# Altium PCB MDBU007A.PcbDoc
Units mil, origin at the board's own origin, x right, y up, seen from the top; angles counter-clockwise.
Board outline 3500 x 3000 mil, 2 copper layers (Top Layer, Bottom Layer), stack 63.4 mil thick; 53 components, 17 nets, 100 pads, 108 vias.
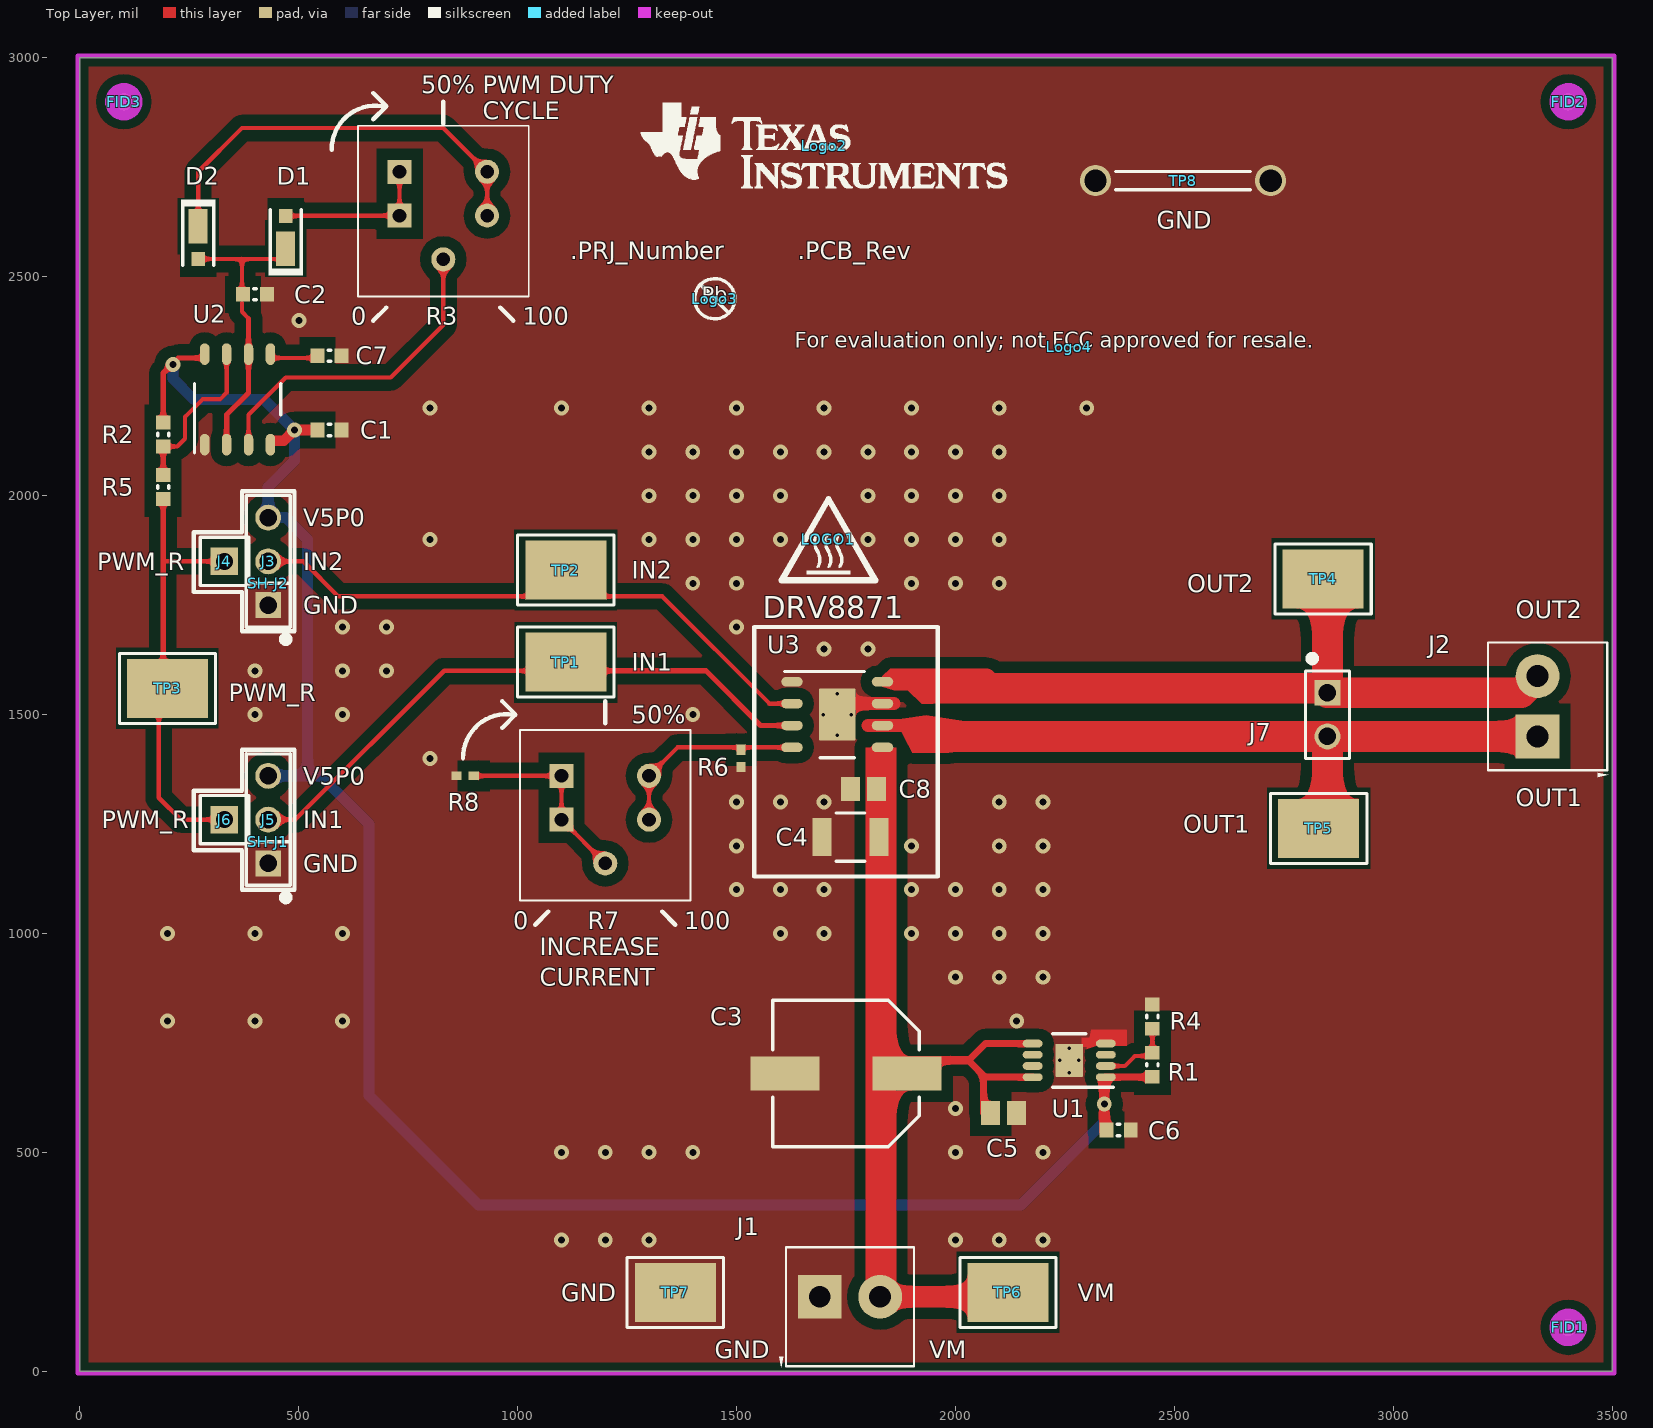
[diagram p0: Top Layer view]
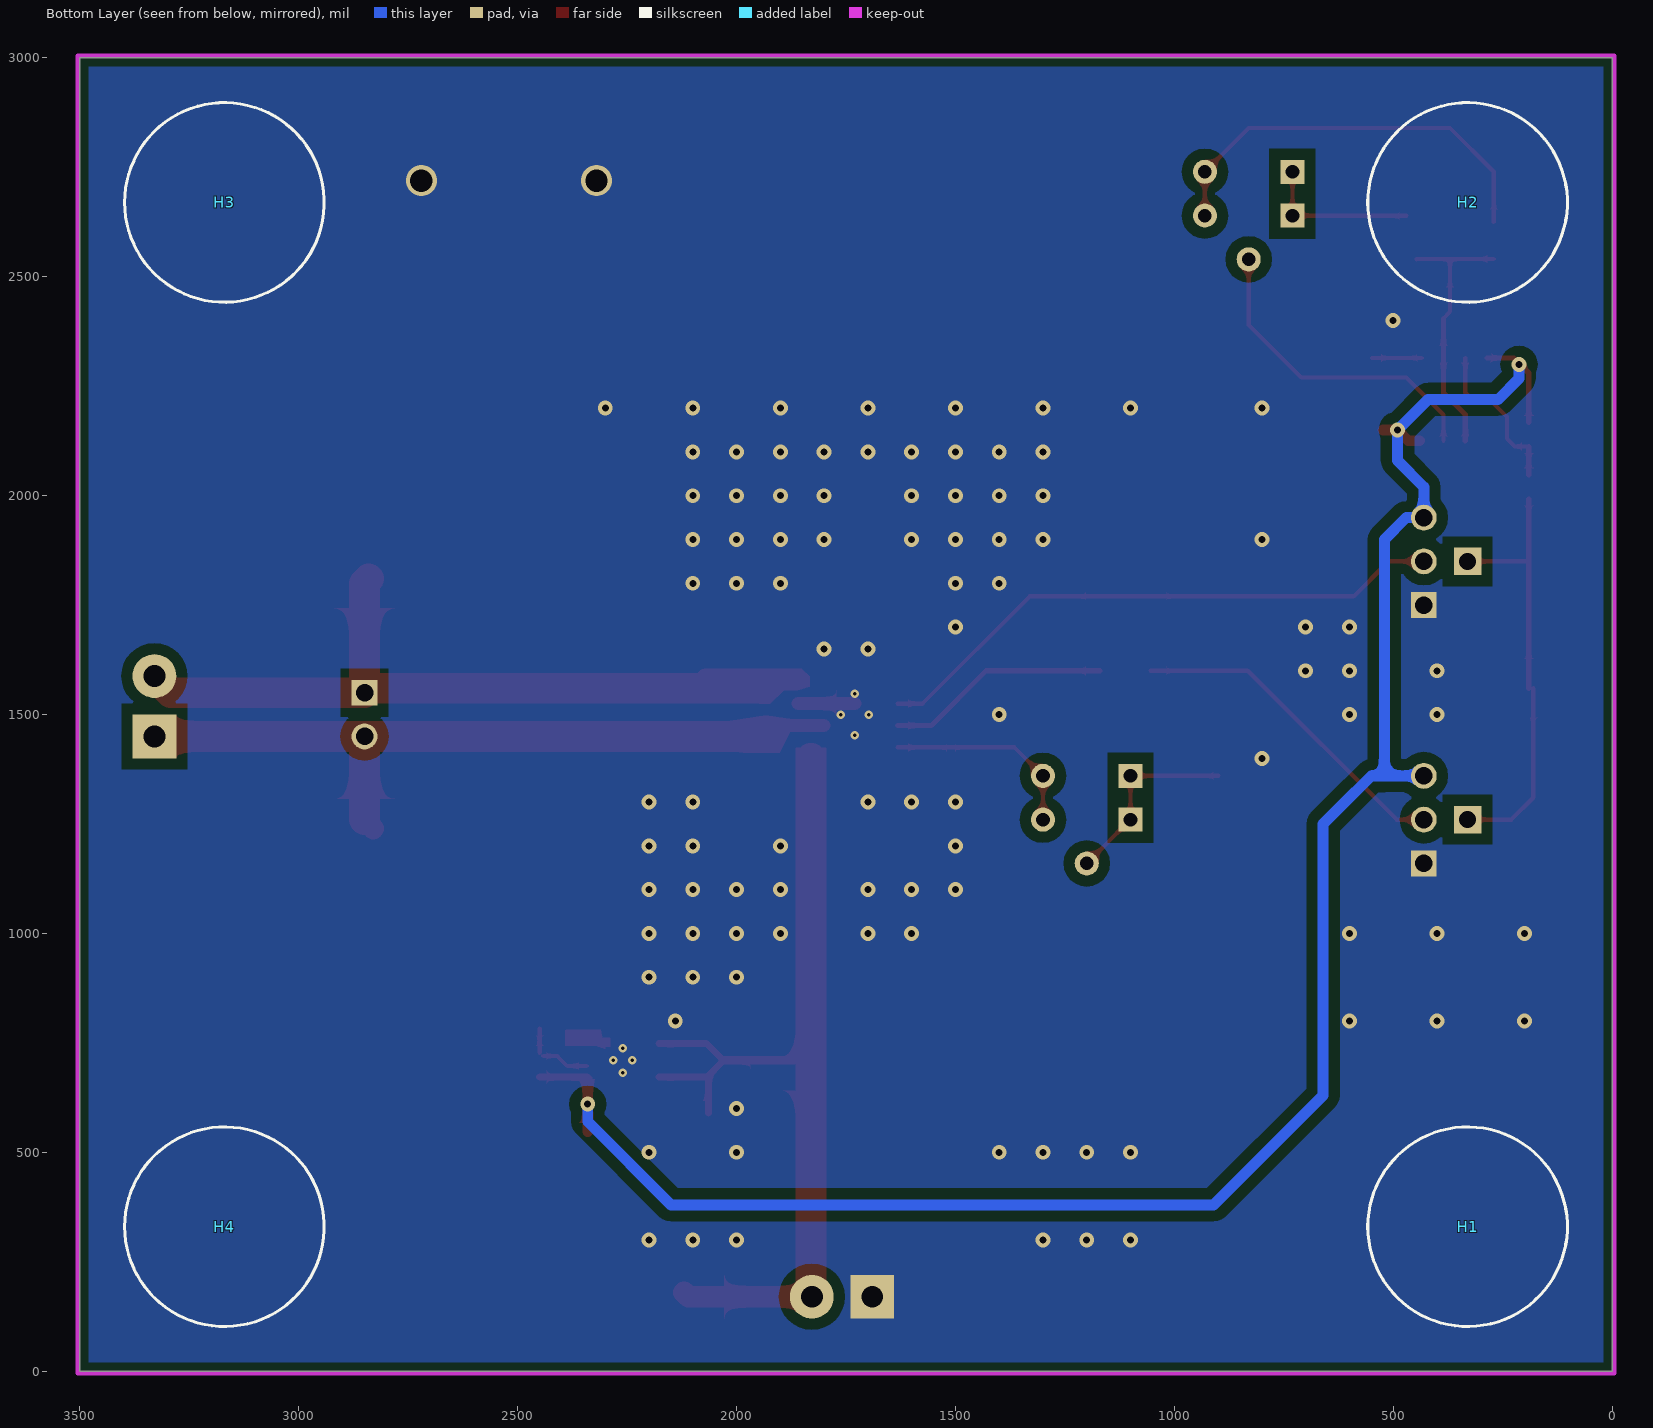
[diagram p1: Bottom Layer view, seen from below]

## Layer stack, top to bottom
Top Solder: solder mask 0.4, Solder Resist, Dk 3.5
Top Layer: signal copper 2.1
Dielectric1: core 59.2, FR-4, Dk 4.8
Bottom Layer: signal copper 2.1
Bottom Solder: solder mask 0.4, Solder Resist, Dk 3.5

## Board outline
0,0 0,3000 3500,3000 3500,0

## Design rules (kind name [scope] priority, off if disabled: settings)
AcuteAngle [All] p1: minimum=4.50000000000000E+0001 checktracksonly=FALSE
AssemblyTestPointUsage [All] p1: valid=2
Clearance Clearance_Keepouts [((IsTrack Or IsArc) And Not InPoly) And IsFree and IsKeepOut vs ((IsTrack Or IsArc) And Not InPoly) And IsFree and IsKeepOut] p1: gap=0
Clearance Clearance_BoardEdge_MountingHoles [OnCopper and InComponentClass('Mounting Holes') vs IsKeepOut] p2: gap=40
Clearance Clearance_BoardEdge_Poly [OnCopper and InPoly vs IsKeepOut] p3: gap=20
Clearance Clearance_BoardEdge [OnCopper and Not InComponentClass('Logo') and not InComponentClass('FiducialMark') and not InRegion(1000,500,4000,800) and Not IsKeepout vs IsKeepOut] p4: gap=75
Clearance Clearance_Poly [InPolygon] p5: gap=25
Clearance [All] p6: gap=7.87
ComponentClearance ComponentClearance_Jumpers [InComponent('J3') or InComponent('J5') vs InComponent('J4') or InComponent('J6')] p1: gap=0 collisioncheckmode=3 verticalgap=0 showdistances=FALSE
ComponentClearance ComponentClearance_MountingHoles_FiducialMarks [InComponentClass('Mounting Holes') vs InComponentClass('FiducialMark')] p2: gap=50 collisioncheckmode=3 verticalgap=10 showdistances=FALSE
ComponentClearance ComponentClearance_Shunt [InComponentClass('Header') vs InComponentClass('Shunt')] p3: gap=0 collisioncheckmode=3 verticalgap=0 showdistances=FALSE
ComponentClearance ComponentClearance_Logo [InComponentClass('Logo')] p4: gap=50 collisioncheckmode=3 verticalgap=10 showdistances=FALSE
ComponentClearance ComponentClearance_ScrewToNut [(HasFootprint('NY PMS 440 0025 PH')) vs (HasFootprint('Keystone_1902C'))] p5: gap=5 collisioncheckmode=3 verticalgap=10 showdistances=FALSE
ComponentClearance ComponentClearance_MountingHoles [InComponentClass('Mounting Holes')] p6: gap=250 collisioncheckmode=3 verticalgap=100000 showdistances=FALSE
ComponentClearance ComponentClearance_SmallPassives [HasFootprint('0201*') or HasFootprint('0402*') or HasFootprint('0508') or HasFootprint('0603*') or HasFootprint('0612') or HasFootprint('0805*') or HasFootprint('0815*') or HasFootprint('0830*') or HasFootprint('1206*') or HasFootprint('1210*') or HasFootprint('1808*') or HasFootprint('1812*') or HasFootprint('1825*') or HasFootprint('2010*') or HasFootprint('2220*') or HasFootprint('2225*') or HasFootprint('2512*') or HasFootprint('2728*') or HasFootprint('3518*') vs HasFootprint('0201*') or HasFootprint('0402*') or HasFootprint('0508') or HasFootprint('0603*') or HasFootprint('0612') or HasFootprint('0805*') or HasFootprint('0815*') or HasFootprint('0830*') or HasFootprint('1206*') or HasFootprint('1210*') or HasFootprint('1808*') or HasFootprint('1812*') or HasFootprint('1825*') or HasFootprint('2010*') or HasFootprint('2220*') or HasFootprint('2225*') or HasFootprint('2512*') or HasFootprint('2728*') or HasFootprint('3518*')] p7: gap=20 collisioncheckmode=3 verticalgap=10 showdistances=FALSE
ComponentClearance ComponentClearance_THtoSMT [IsThruComponent vs IsSMTComponent] p8: gap=10 collisioncheckmode=3 verticalgap=0 showdistances=FALSE
ComponentClearance ComponentClearance_THtoTH [IsThruComponent vs IsThruComponent] p9: gap=10 collisioncheckmode=3 verticalgap=100000 showdistances=FALSE
ComponentClearance ComponentClearance_1 [All] p10: gap=10 collisioncheckmode=3 verticalgap=10 showdistances=FALSE
DiffPairsRouting [All] p1: maxlimit=100 minlimit=10 mostfreqgap=10 toplayer_minwidth=15 toplayer_maxwidth=15 toplayer_prefwidth=15 bottomlayer_minwidth=15 bottomlayer_maxwidth=15 bottomlayer_prefwidth=15 maxuncoupledlength=1000
FabricationTestPointUsage TestPointUsage [All] p1: valid=2 allowmultiple=FALSE
FabricationTestpoint Testpoint [All] p1: side=3 testpointundercomponent=TRUE minsize=40 maxsize=100 preferedsize=60 minholesize=0 maxholesize=40 preferedholesize=32 testpointgrid=1 allowsidetop=TRUE allowsidebottom=TRUE usegrid=TRUE gridtolerance=0.01
FanoutControl Fanout_LCC [IsLCC] p1: bgadir=Out bgaviamode=Centered fanoutstyle=Auto fanoutdirection=Alternating viagrid=1 // Fanout_LCC (Default Rule)
FanoutControl Fanout_BGA [IsBGA] p2: bgadir=Out bgaviamode=Centered fanoutstyle=Auto fanoutdirection=Alternating viagrid=1 // Fanout_BGA (Default Rule)
FanoutControl Fanout_Default [All] p4: bgadir=Out bgaviamode=Centered fanoutstyle=Auto fanoutdirection=Alternating viagrid=1 // Fanout_Default (Default Rule)
FanoutControl Fanout_Small [(CompPinCount < 5)] p5: bgadir=Out bgaviamode=Centered fanoutstyle=Auto fanoutdirection=OutThenIn viagrid=1 // Fanout_Small (Default Rule)
HoleSize [All] p1: absolutevalues=TRUE maxlimit=251 minlimit=7.87 maxpercent=80.000 minpercent=20.000
MinimumAnnularRing MinimumAnnularRing_ThermalPadVias [IsVia and InAnyComponent] p1: minimumring=5.91
MinimumAnnularRing [All] p2: minimumring=9
MinimumSolderMaskSliver MinimumSolderMaskSliver_Logo [InComponentClass('Logo') vs InComponentClass('Logo')] p1: minsoldermaskwidth=0.7
MinimumSolderMaskSliver [All] p2: minsoldermaskwidth=3.94
PlaneConnect [All] p1: planeconnectstyle=Relief reliefexpansion=10 reliefentries=4 reliefconductorwidth=10 reliefairgap=10
PolygonConnect PolygonConnect_2 [All vs IsNamedPolygon('Bottom Layer-No Net')] p1: connectstyle=Direct reliefconductorwidth=10 reliefentries=4 polygonreliefangle="90 Angle" airgapwidth=10
PolygonConnect PolygonConnect_1 [All vs IsNamedPolygon('Top Layer-GND')] p2: connectstyle=Direct reliefconductorwidth=10 reliefentries=4 polygonreliefangle="90 Angle" airgapwidth=10
PolygonConnect [All] p3: connectstyle=Relief reliefconductorwidth=10 reliefentries=4 polygonreliefangle="90 Angle" airgapwidth=10
RoutingVias ThermalPadVias [IsVia and InAnyComponent] p1: holewidth=7.87 width=19.68 viastyle="Through Hole" minholewidth=7.87 minwidth=19.68 maxholewidth=12.99 maxwidth=23.62
RoutingVias [All] p2: holewidth=16 width=34 viastyle="Through Hole" minholewidth=7.87 minwidth=26 maxholewidth=40 maxwidth=65
SilkToBoardRegionClearance [Not ((IsComment or IsDesignator) And (Hide <> 'False')) and not InRegion(1000,500,4000,800)] p1 off:
SilkToSilkClearance SilkToSilkClearance_Pb-FreeLogo [(HasFootprint('Pb-Free_Overlay_Medium') OR HasFootprint('Pb-Free_Overlay_Small')) vs (HasFootprint('Pb-Free_Overlay_Medium') OR HasFootprint('Pb-Free_Overlay_Small'))] p1: silktosilkclearance=0
SilkToSilkClearance [All] p2: silktosilkclearance=4
SilkToSolderMaskClearance "Silk to Solder Mask Opening" [All] p1: minsilkscreentomaskgap=3 clearancetoexposedcopper=FALSE
SolderMaskExpansion [All] p1: expansion=1.97
UnpouredPolygon [All] p1: allowunpoured=FALSE
Width [All] p1: maxlimit=100 minlimit=6 preferedwidth=10 checkconnectedcopper=TRUE
14 further rules are at their usual default settings.

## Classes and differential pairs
component class Logo: Logo2
component class MDBU007A_Hardware: FID1 FID2 FID3 H1 H2 H3 H4 LOGO1 Logo2 Logo3 Logo4 SH-J1 SH-J2 ZZ1 ZZ2 ZZ3 ZZ4
component class FiducialMark: FID1 FID2 FID3
component class AssemblyNote: ZZ1 ZZ2 ZZ3 ZZ4
component class Header: J3 J5 J7
component class MDBU007A: C1 C2 C3 C4 C5 C6 C7 C8 D1 D2 J1 J2 J3 J4 J5 J6 J7 R1 R2 R3 R4 R5 R6 R7 R8 TP1 TP2 TP3 TP4 TP5 TP6 TP7 TP8 U1 U2 U3
component class Shunt: SH-J1 SH-J2

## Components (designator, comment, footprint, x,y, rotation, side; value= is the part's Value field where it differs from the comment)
C1 "C0603C104M4RACTU" 0603L 570,2150 r180 top
C2 "C0603X103K5RACTU" 0603L 400,2460 r180 top
C3 "EEE-FK1J470P" SM_RADIAL_F 1750,680 r180 top
C4 "UMK325AB7106KM-T" 1210_280 1760,1220 r180 top
C5 "08055C105KAT2A" 0805L 2110,590 r0 top
C6 "C0603C225K8PACTU" 0603L 2372.76,551.09 r0 top
C7 "C0603X103K5RACTU" 0603L 570,2320 r180 top
C8 "C0805C104K1RACTU" 0805L 1790,1330 r0 top
D1 "MSS1P4-M3/89A" MicroSMP 470,2590 r90 top
D2 "MSS1P4-M3/89A" MicroSMP 270,2590 r270 top
FID1 "Fiducial" Fiducial10-20 3400,100 r0 top
FID2 "Fiducial" Fiducial10-20 3400,2900 r0 top
FID3 "Fiducial" Fiducial10-20 100,2900 r0 top
H1 "SJ-5303 (CLEAR)" Bumpon_SJ5003Transparent 330,330 r0 bottom
H2 "SJ-5303 (CLEAR)" Bumpon_SJ5003Transparent 330,2670 r90 bottom
H3 "SJ-5303 (CLEAR)" Bumpon_SJ5003Transparent 3170,2670 r0 bottom
H4 "SJ-5303 (CLEAR)" Bumpon_SJ5003Transparent 3170,330 r0 bottom
J1 "ED555/2DS" TERM_BLK_ED555-2DS 1690,170 r0 top
J2 "ED555/2DS" TERM_BLK_ED555-2DS 3330,1450 r90 top
J3 "PEC03SAAN" CONN_PEC03SAAN 430,1850 r90 top
J4 "PEC01SAAN" Sullins_PEC01SAAN 330,1850 r90 top
J5 "PEC03SAAN" CONN_PEC03SAAN 430,1260 r90 top
J6 "PEC01SAAN" Sullins_PEC01SAAN 330,1260 r90 top
J7 "PEC02SAAN" CONN_PEC02SAAN 2850,1500 r270 top
LOGO1 "CAUTION HOT SURFACE" IEC_HotSurface_Small 1710,1900 r0 top
Logo2 "Texas Instruments" TI_Stacked_Overlay_Small 1700,2800 r0 top
Logo3 "Pb-Free Symbol" Pb-Free_Overlay_Small 1450,2450 r0 top
Logo4 "FCC disclaimer" FCC_disclaimer 2260,2340 r0 top
R1 "CRCW06033M40FKEA" 0603L 2450,700 r270 top
R2 "ERJ-3EKF1002V" 0603L 190,2140 r90 top
R3 "3386P-1-503TLF" BOURNS_3386P 830,2650 r0 top
R4 "CRCW06031M07FKEA" 0603L 2450,810 r270 top
R5 "CRCW06030000Z0EA" 0603L 190,2020 r90 top
R6 "CRCW040220K0FKED" 0402L 1510,1400 r270 top
R7 "3386P-1-204TLF" BOURNS_3386P 1200,1270 r0 top
R8 "CRCW040220K0FKED" 0402L 880,1360 r180 top
SH-J1 "969102-0000-DA" SNT-100-BK-G 430,1210 r270 top
SH-J2 "969102-0000-DA" SNT-100-BK-G 430,1800 r90 top
TP1 "5016" Testpoint_Keystone_Compact 1110,1620 r0 top
TP2 "5016" Testpoint_Keystone_Compact 1110,1830 r0 top
TP3 "5016" Testpoint_Keystone_Compact 200,1560 r0 top
TP4 "5016" Testpoint_Keystone_Compact 2840,1810 r0 top
TP5 "5016" Testpoint_Keystone_Compact 2830,1240 r0 top
TP6 "5016" Testpoint_Keystone_Compact 2120,180 r0 top
TP7 "GND" Testpoint_Keystone_Compact 1360,180 r0 top
TP8 "D3082-05" Harwin_D3082-05 2520,2720 r180 top
U1 "TPS7A1601DGNR" DGN0008C_L 2260,710 r180 top
U2 "TLC555CD" D0008A_L 360,2220 r90 top
U3 "DRV8871DDAR" DDA0008H_L 1730,1500 r0 top
ZZ1 "These assemblies are ESD sensitive, ESD precautions shall be observed." AssemblyNote 185,3829.11 r0 top
ZZ2 "These assemblies must be clean and free from flux and all contaminants. Use of no clean flux is not acceptable." AssemblyNote 185,3740.56 r0 top
ZZ3 "These assemblies must comply with workmanship standards IPC-A-610 Class 2, unless otherwise specified." AssemblyNote 185,3652 r0 top
ZZ4 "Shorting plug TP8 shall be raised to minimum height of 250mils above PCB" AssemblyNote 180,3550 r0 top

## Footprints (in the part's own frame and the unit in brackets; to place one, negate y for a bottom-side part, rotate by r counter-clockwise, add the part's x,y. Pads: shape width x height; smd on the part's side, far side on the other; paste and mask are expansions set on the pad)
0402L [mm] "0402 from SM-752 data"
  rect 0.6x0.5 smd: 1(-0.5,0) 2(0.5,0)
  body extent -0.55,-0.3 0.55,0.3, height 0.6
0603L [mm] "0603 from SM-752 data"
  rect 0.8x0.85 smd: 1(-0.7,0) 2(0.7,0)
  silkscreen extent -0.07,-0.33 0.07,0.33, body extent -0.87,-0.47 0.87,0.47, height 0.85
0805L [mm] "0805 from SM-752 data"
  rect 1.1x1.4 smd: 1(-0.75,0) 2(0.75,0)
  body extent -1.1,-0.72 1.1,0.72, height 1.45
1210_280 [mm] "SMD, 2-Leads, Body 3.6x2.8mm, Height 2.8mm"
  rect 1.1x2.2 smd: 1(-1.65,0) 2(1.65,0)
  silkscreen extent -0.84,-1.4 0.84,1.4, body extent -1.8,-1.4 1.8,1.4, height 2.8
AssemblyNote [mil] "Assembly Note"
BOURNS_3386P [mil] "BOURND"
  rect 55x55 hole 31: 1(-100,-10)
  round 55 hole 31: 2(0,-110) 3(100,-10)
  silkscreen extent -195,-195 195,195, body extent -193,-192 193,193, height 201
Bumpon_SJ5003Transparent [mil] "3M Hemispherical Bumpon transparent"
  round 1 on Mech4: 0(0,0)
  silkscreen extent -228,-228 228,228, body extent -217,-218 219,218, height 197
CONN_PEC02SAAN [mm] "SULLINS"
  rect 1.5x1.5 hole 1.016: 1(-1.27,0)
  round 1.5 hole 1.016: 2(1.27,0)
  silkscreen extent -3.45,-1.27 2.54,1.27, body extent -2.54,-1.27 2.54,1.27, height 8.38
CONN_PEC03SAAN [mm] "SULLINS"
  rect 1.5x1.5 hole 1.016: 1(-2.54,0)
  round 1.5 hole 1.016: 2(0,0) 3(2.54,0)
  silkscreen extent -4.72,-1.27 3.81,1.27, body extent -3.84,-1.3 3.84,1.3, height 8.38
D0008A_L [mm] "SOIC, 8-Leads, Body 4.9x3.9mm, Pitch 1.27mm, IPC High Density"
  oval 1.25x0.55 smd: 1(-2.625,1.905) 2(-2.625,0.635) 3(-2.625,-0.635) 4(-2.625,-1.905) 5(2.625,-1.905) 6(2.625,-0.635) 7(2.625,0.635) 8(2.625,1.905)
  silkscreen extent -3.1,-2.5 0.9,2.5, body extent -3,-2.45 3,2.45, height 1.63
DDA0008H_L [mm] "SOIC, 8-Leads, Body 4.9x3.9mm, Pitch 1.27mm, Exposed Pad, IPC High Density"
  rrect100% 1.25x0.55 smd: 1(-2.625,1.905) 2(-2.625,0.635) 3(-2.625,-0.635) 4(-2.625,-1.905) 5(2.625,-1.905) 6(2.625,-0.635) 7(2.625,0.635) 8(2.625,1.905)
  rrect5% 2.13x3 smd: 9(0,0)
  silkscreen extent -3.05,-2.5 1.58,2.5, body extent -3.01,-2.45 3.01,2.45, height 1.7
DGN0008C_L [mm] "TSOP, 8-Leads, Body 3x3mm, Pitch 0.65mm, Thermal Pad 1.98x1.88mm, IPC High Density"
  rrect100% 1.15x0.45 smd: 1(-2.125,0.975) 2(-2.125,0.325) 3(-2.125,-0.325) 4(-2.125,-0.975) 5(2.125,-0.975) 6(2.125,-0.325) 7(2.125,0.325) 8(2.125,0.975)
  rrect6% 1.6x1.92 smd: 9(0,0)
  silkscreen extent -2.55,-1.55 0.95,1.55, body extent -2.46,-1.5 2.46,1.5, height 1.1
FCC_disclaimer [mil]
Fiducial10-20 [mm]
  round 1 smd mask+0.5: 1(0,0)
  Top Layer keep-out circle w1.178: c0,0 r0.5
Harwin_D3082-05 [mm] "Shorting Plug, 10.16mm spacing, TH"
  round 1.8 hole 1.3: 1(-5.08,0) 2(5.08,0)
  silkscreen extent -3.9,-0.53 3.9,0.53, body extent -5.6,-0.52 5.61,0.52, height 6.63
IEC_HotSurface_Small [mil]
  silkscreen extent -107,-93 107,92
MicroSMP [mm] "SMD, 2-Leads, Body 2.2x1.3mm"
  rect 2x1.1 smd: 1(-0.65,0)
  rect 0.8x0.8 smd: 2(1.25,0)
  silkscreen extent -2.2,-1 1.6,1, body extent -1.15,-0.7 1.15,0.7, height 0.75
Pb-Free_Overlay_Small [mil]
  silkscreen extent -46,-46 46,46
SM_RADIAL_F [mm] "8 x 10.2mm:  Panasonic F"
  rect 4x2 smd: 1(-3.55,0) 2(3.55,0)
  silkscreen extent -4.25,-4.25 4.25,4.25, body extent -4.26,-4.26 4.26,4.26, height 10.5
SNT-100-BK-G [mil] "Samtec STEP model"
  round 1 on Mech3: 0(0,0)
  body extent -100,-50 100,50, height 344
Sullins_PEC01SAAN [mm] "SULLINS"
  rect 1.6x1.6 hole 1: 1(0,0)
  silkscreen extent -1.4,-1.4 1.4,1.4, body extent -1.3,-1.3 1.3,1.3, height 8.38
TERM_BLK_ED555-2DS [mil]
  rect 100x100 hole 50: 1(0,0)
  round 100 hole 50: 2(138,0)
  silkscreen extent -93,-161 215,113, body extent -69,-150 207,106, height 323
Testpoint_Keystone_Compact [mil] "Compact SMT test point"
  rect 185x135 smd: 1(0,0)
  silkscreen extent -110,-80 110,80, body extent -75,-56 75,56, height 91
TI_Stacked_Overlay_Small [mil]
  silkscreen extent -418,-98 418,98

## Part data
C1: "CAP, CERM, 0.1 µF, 16 V, +/- 20%, X7R, 0603"
C2 C7: "CAP, CERM, 0.01 µF, 50 V, +/- 10%, X7R, 0603"
C3: "CAP, AL, 47 µF, 63 V, +/- 20%, 0.65 ohm, SMD"
C4: "CAP, CERM, 10 µF, 50 V, +/- 10%, X7R, 1210"
C5: "CAP, CERM, 1 µF, 50 V, +/- 10%, X7R, 0805"
C6: "CAP, CERM, 2.2uF, 10V, +/-10%, X5R, 0603"
C8: "CAP, CERM, 0.1 µF, 100 V, +/- 10%, X7R, 0805"
D1 D2: "Diode, Schottky, 40 V, 1 A, MicroSMP"
FID1 FID2 FID3: "Fiducial mark.  There is nothing to buy or mount."
H1 H2 H3 H4: "Bumpon, Hemisphere, 0.44 X 0.20, Clear"
J1 J2: "Terminal Block, 6A, 3.5mm Pitch, 2-Pos, TH"
J3 J5: "Header, 100mil, 3x1, Tin, TH"
J4 J6: "Header, 1x1, Tin, TH"
J7: "Header, 100mil, 2x1, Tin, TH"
LOGO1: library part IEC_HotSurface, "IEC 61010-1 Hot Surface Warning"
Logo2: library part TI_Logo, "Texas Instrument Corporate Signature"
Logo3: library part Pb-Free
Logo4: library part FCC_disclaimer, "FCC_disclaimer"
R1: "RES, 3.40 M, 1%, 0.1 W, 0603"
R2: "RES, 10.0 k, 1%, 0.1 W, 0603"
R3: library part 3386P-1-503LF, "TRIMMER, 50k ohm, 0.5W, TH"
R4: "RES, 1.07 M, 1%, 0.1 W, 0603"
R5: "RES, 0, 5%, 0.1 W, 0603"
R6 R8: "RES, 20.0 k, 1%, 0.063 W, 0402"
R7: library part 3386P-1-204LF, "TRIMMER, 200k ohm, 0.5W, TH"
SH-J1 SH-J2: "Shunt, 100mil, Gold plated, Black"
TP1 TP2 TP3 TP4 TP5 TP6: "Test Point, Compact, SMT"
TP7: library part 5016, "Test Point, Compact, SMT"
TP8: "1mm Uninsulated Shorting Plug, 10.16mm spacing, TH"
U1: "Single Output LDO, 100 mA, Adjustable 1.2 to 18.5 V Output, 3 to 60 V Input, with Enable and Power Good, 8-pin MSOP (DGN), -40 to 125 degC, Green (RoHS & no Sb/Br)"
U2: "LinCMOS Timer, D0008A"
U3: "H-Bridge PWM Motor Driver with Internal Current Sense, DDA0008H"
ZZ1 ZZ2 ZZ3 ZZ4: library part AssemblyNote

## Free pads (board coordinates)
  rect 55x55 hole 31: 0(730,2740) 0(1100,1360)
  round 55 hole 31: 0(930,2740) 0(1300,1360)

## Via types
v1: diameter 34, hole 16, Top Layer to Bottom Layer, 100 vias
v2: diameter 19.68, hole 7.87, Top Layer to Bottom Layer, 4 vias
v3: diameter 19.68, hole 7.87, Top Layer to Bottom Layer, tented top, 4 vias

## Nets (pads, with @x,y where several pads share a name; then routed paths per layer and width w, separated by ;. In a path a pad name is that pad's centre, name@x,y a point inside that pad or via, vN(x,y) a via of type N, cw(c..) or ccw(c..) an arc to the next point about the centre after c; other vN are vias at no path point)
GND: C1.1 C2.1 C3.2 C4.2 C5.2 C6.2 C7.1 C8.1 J1.1 J3.1 J5.1 R4.1 R6.2 R8.2 TP7.1 TP8.1 TP8.2 U1.4 U1.9 U2.1 U3.1 U3.7 U3.9 | length 130
  Top Layer w30: U3.9@1730,1525 1860,1525
  other v1: 1100,300 1200,300 1300,300 2000,300 2100,300 2200,300 1100,500 1200,500 1300,500 1400,500 2000,500 2200,500 2000,600 200,800 400,800 600,800 2140,800 2000,900 2100,900 2200,900 200,1000 400,1000 600,1000 1600,1000 1700,1000 1900,1000 2000,1000 2100,1000 2200,1000 1500,1100 1600,1100 1700,1100 1900,1100 2000,1100 2100,1100 2200,1100 1500,1200 1900,1200 2100,1200 2200,1200 1500,1300 1600,1300 1700,1300 2100,1300 2200,1300 800,1400 400,1500 600,1500 1400,1500 400,1600 600,1600 700,1600 1700,1650 1800,1650 600,1700 700,1700 1500,1700 1400,1800 1500,1800 1900,1800 2000,1800 2100,1800 800,1900 1300,1900 1400,1900 1500,1900 1600,1900 1800,1900 1900,1900 2000,1900 2100,1900 1300,2000 1400,2000 1500,2000 1600,2000 1800,2000 1900,2000 2000,2000 2100,2000 1300,2100 1400,2100 1500,2100 1600,2100 1700,2100 1800,2100 1900,2100 2000,2100 2100,2100 800,2200 1100,2200 1300,2200 1500,2200 1700,2200 1900,2200 2100,2200 2300,2200 500,2400
  other v2: 2260,682.05 2238.35,710 2281.65,710 2260,737.95
  other v3: 1730,1452.76 1697.91,1500 1762.09,1500 1730,1547.24
ILIM: pad.0@1300,1360 R6.1 R7.3 U3.4 | length 458.5
  Top Layer w10: R7.3 1300,1360 1365,1425 U3.4@1631.57,1425
IN1: J5.2 TP1.1 U3.3 | length 1277.9
  Top Layer w10: J5.2 491.98,1260 831.98,1600 TP1.1@1053.76,1600
  Top Layer w12: TP1.1@1170,1600 1430,1600 1555,1475 U3.3@1631.57,1475
IN2: J3.2 TP2.1 U3.2 | length 1336.2
  Top Layer w10: J3.2 510,1850 590,1770 1330,1770 1575,1525 U3.2@1631.57,1525
NetC7_2: C7.2 U2.5 | length 113.3
  Top Layer w10: U2.5@435,2314.49 C7.2@548.35,2314.49
NetD1_2: D1.2 pad.0@730,2740 R3.1 | length 360
  Top Layer w10: D1.2 R3.1 pad.0@730,2740
NetD2_1: D2.1 pad.0@930,2740 R3.3 | length 957.4
  Top Layer w10: D2.1@270,2625.43 270,2740 370,2840 830,2840 930,2740 R3.3
NetR1_1: R1.1 R4.2 U1.2 | length 163.3
  Top Layer w10: U1.2@2342.68,697.2 2387.2,697.2 2410,720 R1.1@2441.7,720 ; R1.1 R4.2
NetR7_1: pad.0@1100,1360 R7.1 R7.2 R8.1 | length 441.7
  Top Layer w10: R8.1 1100,1360 R7.1 R7.2
OUT1: J2.1 J7.2 TP5.1 U3.6 | length 1752.4
  Top Layer w30: 1800,1475 1920,1475
  Top Layer w50: TP5.1 TP5.1@2850,1260
  Top Layer w70: 1920,1460 1930,1450 J7.2 ; TP5.1@2850,1260 J7.2 ; J2.1 J7.2
OUT2: J2.2 J7.1 TP4.1 U3.8 | length 1878.9
  Top Layer w50: 1865.16,1580 2070,1580
  Top Layer w70: 1940,1560 2840,1560 J7.1 ; TP4.1 2850,1800 J7.1 ; J2.2 3292,1550 J7.1
PWM: R2.1 R5.2 U2.7 | length 369.4
  Top Layer w10: R2.1 222.44,2112.44 240,2130 240,2180 280,2220 320,2220 335,2235 U2.7@335,2314.49
  Top Layer w12: R5.2 R2.1
PWM_R: J4.1 J6.1 R5.1 TP3.1 | length 993.2
  Top Layer w10: TP3.1@180,1560 180,1310 230,1260 J6.1 ; 190,1850 J4.1
  Top Layer w12: TP3.1@190,1560 190,1850 R5.1
THRES: C2.2 D1.1 D2.2 U2.2 U2.6 | length 608.8
  Top Layer w10: D2.2 446.07,2540.79 446.23,2540.63 ; 370,2440.27 370,2420 385,2405 ; C2.2@370,2450 370,2540.79
  Top Layer w12: U2.2@335,2125.51 335,2185 385,2235 385,2314.49 385,2405
TLC555_OUT: R3.2 U2.3 | length 739.4
  Top Layer w10: U2.3@385,2125.51 385,2185 470,2270 710,2270 830,2390 R3.2
V5P0: C1.2 C6.1 J3.3 J5.3 R1.2 R2.2 U1.1 U2.4 U2.8 | length 4576.2
  Top Layer w12: R2.2 190,2280 224.49,2314.49 U2.8@285,2314.49
  Top Layer w16: U1.1@2342.68,671.61 R1.2@2450,671.61
  Top Layer w25: U2.4@440,2125.51 465.51,2125.51 v1(490,2150) 523.69,2150 ; C6.1@2340,547.81 v1(2340,610) 2340,665.3 U1.1@2342.68,667.97
  Bottom Layer w25: v1(212.48,2300) 212.48,2267.52 260,2220 420,2220 v1(490,2150) 490,2080 430,2020 J3.3 470,1950 520,1900 520,1360 ; J5.3 520,1360 ; v1(2340,610) 2340,570 2150,380 910,380 660,630 660,1250 620,1290 550,1360 520,1360
VM: C3.1 C4.1 C5.1 C8.2 J1.2 TP6.1 U1.5 U1.8 U3.5 | length 2108
  Top Layer w16: C5.1@2064.57,590 2064.57,675.43 ; U1.8@2177.32,671.61 2068.39,671.61 2064.57,675.43 ; U1.5@2177.32,748.39 2068.39,748.39 2030,710 2064.57,675.43
  Top Layer w20: C3.1@1860,710 2030,710
  Top Layer w50: J1.2 2110,170 TP6.1
  Top Layer w70: J1.2@1830,170 1830,1400
pads on no net: FID1.1 FID2.1 FID3.1 H1.0 H2.0 H3.0 H4.0 SH-J1.0 SH-J2.0 U1.3 U1.6 U1.7

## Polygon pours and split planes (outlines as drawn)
GND on Top Layer "Top Layer-GND" (solid, remove dead copper, pour order 4): 0,0 0,3000 3500,3000 3500,0
GND on Bottom Layer "Bottom Layer-No Net" (solid, remove dead copper, pour order 6): 0,0 0,3000 3500,3000 3500,0

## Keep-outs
Keep-Out Layer:
  lines w10: -5,-5 3505,-5 3505,3005 -5,3005 -5,-5 ; -5,0 ccw(c0,0) 0,-5 cw(c0,0) -5,0
  text ".Layer_Name" at 577,-858.49 h60

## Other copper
Top Layer:
  region net GND: 2288.5,739.87 2318.96,742.51 2318.96,754.51 2311.47,762 2289,762
  region net OUT1: 1879,1490 1933,1498 2023,1485 2003,1415 1985,1413 1901,1413 1892,1431 1877.64,1460
  region net OUT2: 1833,1563 1859,1555 1891,1555 1923,1525 1949,1525 1949,1605 1851,1605 1833,1587
  region net VM: 1795,1385 1795,1424 1865,1424 1865,1385
  region net GND: 2298.33,735.79 2323.2,743.11 2390.83,743.11 2390.83,779.17 2390,780 2310,780 2307.26,763.06
  text ".Layer_Name" at 577,-858.49 h60
Bottom Layer:
  text ".Layer_Name" at 577,-858.49 h60

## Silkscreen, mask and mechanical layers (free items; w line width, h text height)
Top Overlay:
  lines w10: 575.02,2790.05 cw(c675.02,2791.13) 690,2890 ; 670,2400 700,2430 ; 670,2860 700,2890 670,2920 ; 830,2850 830,2900 ; 875.02,1400.05 cw(c975.02,1401.13) 990,1500 ; 960,2430 990,2400 ; 965,1470 995,1500 965,1530 ; 1040,1020 1070,1050 ; 1200,1480 1200,1530 ; 1330,1050 1360,1020 ; 260,1190 260,1326.09 370,1326.09 370,1420 490,1420 490,1100 370,1100 370,1190 260,1190 ; 260,1780 260,1916.09 370,1916.09 370,2010 490,2010 490,1690 370,1690 370,1780 260,1780 ; 1540,1130 1960,1130 1960,1700 1540,1700 1540,1130
  text "50%" at 780,2920 h40
  text "PWM DUTY" at 920,2920 h40
  text "CYCLE" at 920,2860 h40
  text "GND" at 2460,2610 h40
  text ".PRJ_Number" at 1120,2540 h40
  text ".PCB_Rev" at 1640,2540 h40
  text "0" at 620,2390 h40
  text "100" at 1011,2390 h40
  text "V5P0" at 510,1930 h40
  text "PWM_R" at 40,1830 h40
  text "IN2" at 510,1830 h40
  text "IN2" at 1260,1810 h40
  text "OUT2" at 2530,1780 h40
  text "GND" at 510,1730 h40
  text "DRV8871" at 1560,1720 h50
  text "OUT2" at 3280,1720 h40
  text "IN1" at 1260,1600 h40
  text "PWM_R" at 340,1530 h40
  text "50%" at 1260,1480 h40
  text "V5P0" at 510,1340 h40
  text "OUT1" at 3280,1290 h40
  text "PWM_R" at 50,1240 h40
  text "IN1" at 510,1240 h40
  text "OUT1" at 2520,1230 h40
  text "GND" at 510,1140 h40
  text "0" at 990,1010 h40
  text "100" at 1380,1010 h40
  text "INCREASE" at 1050,950 h40
  text "CURRENT" at 1050,880 h40
  text "VM" at 2280,160 h40
  text "GND" at 1450,30 h40
  text "VM" at 1940,30 h40
  text ".Layer_Name" at 577,-858.49 h60
Bottom Overlay:
  text ".Layer_Name" at 577,-858.49 h60
Top Paste:
  text ".Layer_Name" at 577,-858.49 h60
Bottom Paste:
  text ".Layer_Name" at 577,-858.49 h60
Top Solder:
  text ".Layer_Name" at 577,-858.49 h60
  text ".Layer_Name" at 577,-858.49 h60
Bottom Solder:
  text ".Layer_Name" at 577,-858.49 h60
Drill Guide:
  text ".Layer_Name" at 577,-858.49 h60
M1 Board Outline:
  the board outline again, w10
  text ".Layer_Name" at 577,-858.49 h60
M2 Board Dimensions:
  rectangle: 0,-275 125,-150
  rectangle: 125,-400 500,-275
  lines w7: 0,-275 1000,-275 ; 125,-400 125,-150 ; 250,-400 250,-150 ; 500,-400 500,-150 ; 750,-400 750,-150 ; 0,-400 1000,-400 1000,-150 0,-150 0,-400
  text ".Layer_Name" at 577,-858.49 h60
M3 3D STEP Top:
  text ".Layer_Name" at 577,-858.49 h60
M4 3D STEP Bottom:
  text ".Layer_Name" at 577,-858.49 h60
M5 Assembly Top:
  lines w10: -292,-930.17 6308,-930.17 ; -292,-726.83 6310,-726.83 ; -292,-523.5 -292,-1133.5 3713,-1133.5 6310,-1133.5 6310,-523.5 -291.5,-523.5 -291.5,-1133.5 1284,-1133.5 ; 2173,-1133.5 2173,-523.5 ; 3440,-726.83 3440,-523.5 ; 4280,-726.83 4280,-523.5 ; 4902,-1140 4902,-937.17
  text "COMPONENTS MARKED 'DNP' SHOULD NOT BE POPULATED." at 1153.5,-318.5 h60
  text "ASSEMBLY VARIANT:" at 1153,-434 h60
  text ".VariantName" at 2189,-434 h60
  text "PCB VIEWED FROM TOP SIDE" at -228.5,-655.67 h60
  text "BOARD #:" at 2248,-655.67 h60
  text ".PRJ_Number" at 2793.5,-655.67 h60
  text "REV:" at 3638,-655.67 h60
  text ".PCB_Rev" at 3929.5,-655.67 h60
  text "SVN REV:" at 4476,-655.67 h60
  text ".VersionControl_RevNumber" at 4982,-655.67 h60
  text "TID #:" at 2248,-859 h60
  text ".TID" at 2793.5,-859 h60
  text "PLOT NAME =" at -228.5,-1064.34 h60
  text ".plot_File_Name" at 577,-1064.34 h60
  text "GENERATED    :" at 2250,-1064.34 h60
  text ".Print_Date" at 3119.5,-1064.34 h60
  text ".Print_Time" at 3848.5,-1064.34 h60
  text "TEXAS INSTRUMENTS" at 5113,-1064.34 h60
M6 Assembly Bottom:
  lines w10: -292.5,-727.33 6309.5,-727.33 ; -290.5,-930.67 6309.5,-930.67 ; 1115.5,-1140.5 1115.5,-937.67 ; 1737.5,-727.33 1737.5,-524 ; 2577.5,-727.33 2577.5,-524 ; 3844.5,-1134 3844.5,-524 ; 4733.5,-1134 6309,-1134 6309,-524 -292.5,-524 -292.5,-1134 2304.5,-1134 6309.5,-1134 6309.5,-524
  text "COMPONENTS MARKED 'DNP' SHOULD NOT BE POPULATED." at 6102,-318 h60
  text ".VariantName" at 5058,-434 h60
  text "ASSEMBLY VARIANT:" at 6097,-434 h60
  text ".VersionControl_RevNumber" at 1035.5,-656.17 h60
  text "SVN REV:" at 1541.5,-656.17 h60
  text ".PCB_Rev" at 2088,-656.17 h60
  text "REV:" at 2379.5,-656.17 h60
  text ".PRJ_Number" at 3224,-656.17 h60
  text "BOARD #:" at 3769.5,-656.17 h60
  text "PCB VIEWED FROM BOTTOM SIDE" at 6246,-656.17 h60
  text ".TID" at 3224,-859.5 h60
  text "TID #:" at 3769.5,-859.5 h60
  text "TEXAS INSTRUMENTS" at 904.5,-1064.84 h60
  text ".Print_Time" at 2169,-1064.84 h60
  text ".Print_Date" at 2898,-1064.84 h60
  text "GENERATED    :" at 3767.5,-1064.84 h60
  text ".plot_File_Name" at 5440.5,-1064.84 h60
  text "PLOT NAME =" at 6246,-1064.84 h60
M9 Title Sheet:
  drawing of 57 lines, arcs and shapes, not listed
  text "1" at 739.84,8036.5 h70
  text "2" at 3235.5,8036.5 h70
  text "3" at 5724.84,8036.5 h70
  text "4" at 8231.51,8036.5 h70
  text "5" at 10730.5,8036.5 h70
  text "6" at 13235.5,8036.5 h70
  text "A" at -416.5,6893.5 h70
  text "A" at 14383.5,6893.5 h70
  text "B" at -416.5,4513.5 h70
  text "B" at 14383.5,4513.5 h70
  text "C" at -416.5,2138.5 h70
  text "C" at 14383.5,2138.5 h70
  text "PROJECT TITLE:" at 11343.5,277.5 h45
  text ".PRJ_Title" at 11393.5,144.17 h70
  text "DESIGNED FOR:" at 11343.5,-23.5 h45
  text ".PRJ_Customer" at 11393.5,-163.5 h70
  text "D" at -416.5,-231.5 h70
  text "D" at 14383.5,-231.5 h70
  text "FILE NAME:" at 11343.5,-323.5 h45
  text ".PCB_File_Name_No_Path" at 11393.5,-443.5 h70
  text "Texas Instruments (TI) and/or its licensors do not warrant the accuracy or completeness of this specification" at 6374,-605.34 h45
  text "ENGINEER:" at 11343.5,-613.5 h45
  text "LAYOUT BY:" at 12848.5,-613.5 h45
  text "or any information contained therein. TI and/or its licensors do not warrant that this design will meet" at 6329.01,-718 h45
  text ".PRJ_Engineer" at 11393.5,-768.49 h70
  text ".PCB_Layout" at 12899,-768.49 h70
  text "the specifications, will be suitable for your application or fit for any particular purpose, or will operate in" at 6329.01,-830.67 h45
  text ".Layer_Name" at 577,-858.49 h60
  text "ALTIUM DESIGNER VERSION:" at 12848.5,-923.5 h45
  text "an implementation. TI and/or its licensors do not warrant that the design is production worthy. You should" at 6329.01,-943.33 h45
  text "completely validate and test your design implementation to confirm the system functionality for your application." at 6374,-1056 h45
  text ".print_Scale" at 11393.5,-1056.83 h70
  text ".Application_BuildNumber" at 12899,-1056.83 h70
  text "1" at 739.84,-1263.5 h70
  text "2" at 3235.5,-1263.5 h70
  text "3" at 5724.84,-1263.5 h70
  text "4" at 8231.51,-1263.5 h70
  text "5" at 10730.5,-1263.5 h70
  text "6" at 13235.5,-1263.5 h70
M10 Fab Notes:
  drawing of 185 lines, arcs and shapes, not listed
  text "DESIGN INFORMATION" at 12381.02,5910 h60
  text "MIN. TRACK WIDTH:" at 11736.46,5730 h60
  text "10" at 12832.7,5730 h60
  text "MIL" at 12987.46,5730 h60
  text "MIN. CLEARANCE:" at 11736.46,5598 h60
  text "0.2" at 12772.7,5598 h60
  text "mm" at 12987.46,5598 h60
  text "MIN. VIA PAD SIZE:" at 11736.46,5466 h60
  text "24" at 12802.71,5466 h60
  text "MIL" at 12987.46,5466 h60
  text "0.05mm (2MIL)" at 12431.46,5324.29 h60
  text "MINIMUM ANNULAR RING" at 11407.23,5320 h60
  text "EXTERNAL" at 13139.46,5320 h60
  text "PER" at 11607.23,5202 h60
  text "IPC-D-275 CLASS 2 LEVEL C" at 11827.23,5202 h60
  text "MIL, HOLES" at 13315.46,5089.71 h60
  text "+/-" at 12923,5089 h60
  text "+/-" at 13777,5089 h60
  text "REGISTRATION TOLERANCES:" at 11407.23,5084 h60
  text "METAL" at 12607,5084 h60
  text "5" at 13183.2,5084 h60
  text "3" at 14016.2,5084 h60
  text "MIL" at 14132.46,5084 h60
  text "MATERIAL:" at 11332.46,4874.54 h60
  text "FR-4 High Tg" at 12318.9,4734.21 h60
  text "FR-408" at 11753.46,4725.64 h60
  text "X" at 12165.46,4725.64 h60
  text "OTHER" at 13241.46,4725.64 h60
  text "62 MIL (1.6mm) +/-10%" at 12073.56,4562.92 h60
  text "THICKNESS:" at 11407.23,4558.64 h60
  text "X" at 11945.4,4558.64 h60
  text "OTHER" at 13358.46,4558.64 h60
  text "TOLERANCE:" at 11407.23,4400.64 h60
  text "X" at 12246.53,4400.64 h60
  text "ANSI IPC-6012 TYPE 3 CLASS 2" at 12433.48,4400.64 h60
  text "OTHER +/-" at 12433.46,4244.64 h60
  text "BOW & TWIST:" at 11407.23,4087.64 h60
  text "X" at 12246.53,4087.64 h60
  text "ANSI IPC-6012 TYPE 3 CLASS 2" at 12433.48,4087.64 h60
  text "OTHER +/-" at 12433.46,3929.13 h60
  text "DRILLING:" at 11332.46,3790.64 h60
  text "REFERENCE:" at 11407.23,3673.64 h60
  text "X" at 12055.46,3673.64 h60
  text "AS SHOWN" at 12242.46,3673.64 h60
  text "X" at 12956.46,3673.64 h60
  text "NC_DRILL FILES" at 13093.46,3673.64 h60
  text "PTH MIN COPPER THICKNESS:" at 11407.23,3515.64 h60
  text "X" at 12757.46,3515.64 h60
  text "1MIL" at 12894.46,3515.64 h60
  text "OTHER" at 13391.46,3515.64 h60
  text "BOARD FINISH:" at 11332.46,3356.64 h60
  text "SILKSCREEN:" at 11487.68,3238.64 h60
  text "X" at 12436.46,3238.64 h60
  text "TOP" at 12562.46,3238.64 h60
  text "BOTTOM" at 13073.46,3238.64 h60
  text "SILKSCREEN COLOR:" at 11487.68,3071.64 h60
  text "X" at 12435.42,3071.64 h60
  text "WHITE" at 12562.46,3071.64 h60
  text "OTHER" at 13073.46,3071.64 h60
  text "SOLDER RESIST COLOR:" at 11487.68,2901.64 h60
  text "X" at 12055.42,2742.44 h60
  text "GREEN" at 12182.46,2742.44 h60
  text "BLUE" at 12773.46,2742.44 h60
  text "OTHER" at 13311.46,2742.44 h60
  text "IMMERSION GOLD (ENIG)" at 12393.46,2553.92 h60
  text "ENEPIG" at 13731,2550.64 h60
  text "SURFACE FINISH:" at 11332.46,2549.64 h60
  text "X" at 12206.51,2549.64 h60
  text "IMM. TIN/SILVER OR EQUIV" at 11662,2392.64 h60
  text "OTHER" at 13093.46,2392.64 h60
  text "ARRAY/PANEL:" at 11332.46,2213.64 h60
  text "CUT AND TRIM PER MECH LAYER 1" at 12393.46,2209.35 h60
  text "N.C. ROUTE" at 12393.46,2057.64 h60
  text "X" at 13072.46,2057.64 h60
  text "V. SCORE" at 13259.46,2057.64 h60
  text "CERTIFICATION:" at 11332.46,1920.64 h60
  text "MATERIALS AND WORKMANSHIP FOR ALL PCBS" at 12057.46,1920.64 h60
  text "TO MEET OR EXCEED THE REQUIREMENTS OF:" at 12057.46,1822.64 h60
  text "X" at 11683.96,1686.13 h60
  text "ANSI IPC-A-600F CLASS ->" at 11822.96,1686.13 h60
  text "X" at 13462.02,1686.13 h60
  text "2" at 13580.96,1686.14 h60
  text "1" at 13265.96,1684.64 h60
  text "3" at 13934.96,1684.64 h60
  text "X" at 11686.02,1526.64 h60
  text "UL 94V-0" at 11822.96,1526.64 h60
  text "X" at 12498.02,1526.64 h60
  text "RoHS" at 12634.96,1526.64 h60
  text "OTHER" at 13279.36,1526.64 h60
  text "PER ORDER" at 13676.42,1526.64 h60
  text "ADDITIONAL REQUIREMENTS:" at 11332.46,1385.64 h60
  text "MICROSECTION:" at 11407.23,1270.64 h60
  text "YES" at 12312.96,1270.64 h60
  text "REQUIRED" at 13174.46,1114.49 h60
  text "BARE BOARD ELEC. TEST:" at 11407.23,1111.64 h60
  text "NONE" at 12712.96,1111.64 h60
  text "X" at 13047.46,1111.64 h60
  text "PER ORDER" at 13766.46,1111.64 h60
  text "MANUFACTURER'S UL:" at 11407.23,954.64 h60
  text "RAIL" at 12572.96,950.35 h60
  text "METAL" at 13064.77,950.35 h60
  text "X" at 13440,950 h60
  text "SILK" at 13576.46,950.35 h60
  text ".Layer_Name" at 577,-858.49 h60
M11 Gerber Information:
  lines w10: -292,-930.17 6308,-930.17 ; -292,-726.83 6310,-726.83 ; -292,-523.5 -292,-1133.5 3713,-1133.5 6310,-1133.5 6310,-523.5 -291.5,-523.5 -291.5,-1133.5 1284,-1133.5 ; 2173,-1133.5 2173,-523.5 ; 3440,-726.83 3440,-523.5 ; 4280,-726.83 4280,-523.5 ; 4902,-1140 4902,-937.17
  text "ALL ARTWORK VIEWED FROM TOP SIDE" at -228.5,-655.67 h60
  text "BOARD #:" at 2248,-655.67 h60
  text ".PRJ_Number" at 2793.5,-655.67 h60
  text "REV:" at 3638,-655.67 h60
  text ".PCB_Rev" at 3929.5,-655.67 h60
  text "SVN REV:" at 4476,-655.67 h60
  text ".VersionControl_RevNumber" at 4982,-655.67 h60
  text "LAYER NAME =" at -228.5,-858.49 h60
  text "TID #:" at 2248,-859 h60
  text ".TID" at 2793.5,-859 h60
  text "PLOT NAME =" at -228.5,-1064.34 h60
  text ".plot_File_Name" at 577,-1064.34 h60
  text "GENERATED    :" at 2250,-1064.34 h60
  text ".Print_Date" at 3119.5,-1064.34 h60
  text ".Print_Time" at 3848.5,-1064.34 h60
  text "TEXAS INSTRUMENTS" at 5113,-1064.34 h60
M12 Stackup:
  drawing of 165 lines, arcs and shapes, not listed
  text "Layer" at 9760,7780 h60
  text "Name" at 10169.91,7780 h60
  text "Material" at 11029.68,7780 h60
  text "Thickness" at 11889.45,7780 h60
  text "Constant" at 12539.28,7780 h60
  text "Board Layer Stack" at 13109.14,7780 h60
  text "1" at 9760,7660 h60
  text "Top Overlay" at 10169.91,7660 h60
  text "2" at 9760,7540 h60
  text "Top Solder" at 10169.91,7540 h60
  text "Solder Resist" at 11029.68,7540 h60
  text "0.40mil" at 11889.45,7540 h60
  text "3.5" at 12539.28,7540 h60
  text "3" at 9760,7420 h60
  text "Top Layer" at 10169.91,7420 h60
  text "Copper" at 11029.68,7420 h60
  text "2.10mil" at 11889.45,7420 h60
  text "4" at 9760,7300 h60
  text "Dielectric1" at 10169.91,7300 h60
  text "FR-4" at 11029.68,7300 h60
  text "59.20mil" at 11889.45,7300 h60
  text "4.8" at 12539.28,7300 h60
  text "5" at 9760,7180 h60
  text "Bottom Layer" at 10169.91,7180 h60
  text "Copper" at 11029.68,7180 h60
  text "2.10mil" at 11889.45,7180 h60
  text "6" at 9760,7060 h60
  text "Bottom Solder" at 10169.91,7060 h60
  text "Solder Resist" at 11029.68,7060 h60
  text "0.40mil" at 11889.45,7060 h60
  text "3.5" at 12539.28,7060 h60
  text ".Layer_Name" at 577,-858.49 h60
M13 Component Bodies Top:
  text ".Layer_Name" at 577,-858.49 h60
M14 Component Bodies Bottom:
  text ".Layer_Name" at 577,-858.49 h60
M15 Courtyards Top:
  text ".Layer_Name" at 577,-858.49 h60
M16 Courtyards Bottom:
  text ".Layer_Name" at 577,-858.49 h60
Drill Drawing:
  circle w1: c4592.8,2770.83 r24.91
  lines w1: 4567.89,1849.17 4617.71,1849.17 4617.71,1898.99 4567.89,1898.99 4567.89,1849.17 ; 4567.89,2023.54 4592.8,1998.63 4617.71,2023.54 4592.8,2048.45 4567.89,2023.54 ; 4567.89,2148.09 4567.89,2160.54 4580.35,2173 4567.89,2185.45 4567.89,2197.91 4580.35,2197.91 4592.8,2185.45 4605.26,2197.91 4617.71,2197.91 4617.71,2185.45 4605.26,2173 4617.71,2160.54 4617.71,2148.09 4605.26,2148.09 4592.8,2160.54 4580.35,2148.09 4567.89,2148.09 ; 4567.89,2310 4580.35,2310 4580.35,2297.54 4605.26,2297.54 4605.26,2310 4617.71,2310 4617.71,2334.91 4605.26,2334.91 4605.26,2347.36 4580.35,2347.36 4580.35,2334.91 4567.89,2334.91 4567.89,2310 ; 4567.89,2459.46 4580.35,2459.46 4592.8,2447 4605.26,2459.46 4617.71,2459.46 4605.26,2471.91 4617.71,2484.37 4605.26,2484.37 4592.8,2496.82 4580.35,2484.37 4567.89,2484.37 4580.35,2471.91 4567.89,2459.46 ; 4567.89,2646.28 4617.71,2646.28 4592.8,2596.46 4567.89,2646.28 ; 4577.85,1859.13 4607.75,1859.13 4607.75,1889.02 4577.85,1889.02 4577.85,1859.13
  lines w12: 4500,1804.33 6619.4,1804.33 ; 4500,2850.54 6619.4,2850.54 ; 4870.67,1654.87 4870.67,3000 ; 5227.78,1654.87 5227.78,3000 ; 5889.79,1654.87 5889.79,3000 ; 6174.14,1654.87 6174.14,3000 ; 4500,1654.87 6619.4,1654.87 6619.4,3000 4500,3000 4500,1654.87
  text "Symbol" at 4589.68,2895.38 h72
  text "Quantity" at 4915.51,2895.38 h72
  text "Finished Hole Size" at 5272.62,2895.38 h72
  text "Plated" at 5934.62,2895.38 h72
  text "Hole Type" at 6218.98,2895.38 h72
  text "8" at 4915.51,2745.92 h60
  text "7.87mil (0.200mm)" at 5272.62,2745.92 h60
  text "PTH" at 5934.62,2745.92 h60
  text "Round" at 6218.98,2745.92 h60
  text "100" at 4915.51,2596.46 h60
  text "16.00mil (0.406mm)" at 5272.62,2596.46 h60
  text "PTH" at 5934.62,2596.46 h60
  text "Round" at 6218.98,2596.46 h60
  text "10" at 4915.51,2447 h60
  text "31.00mil (0.787mm)" at 5272.62,2447 h60
  text "PTH" at 5934.62,2447 h60
  text "Round" at 6218.98,2447 h60
  text "2" at 4915.51,2297.54 h60
  text "39.37mil (1.000mm)" at 5272.62,2297.54 h60
  text "PTH" at 5934.62,2297.54 h60
  text "Round" at 6218.98,2297.54 h60
  text "8" at 4915.51,2148.09 h60
  text "40.00mil (1.016mm)" at 5272.62,2148.09 h60
  text "PTH" at 5934.62,2148.09 h60
  text "Round" at 6218.98,2148.09 h60
  text "4" at 4915.51,1998.63 h60
  text "50.00mil (1.270mm)" at 5272.62,1998.63 h60
  text "PTH" at 5934.62,1998.63 h60
  text "Round" at 6218.98,1998.63 h60
  text "2" at 4915.51,1849.17 h60
  text "51.18mil (1.300mm)" at 5272.62,1849.17 h60
  text "PTH" at 5934.62,1849.17 h60
  text "Round" at 6218.98,1849.17 h60
  text "134 Total" at 4915.51,1699.71 h60
  text ".Layer_Name" at 577,-858.49 h60

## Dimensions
0,0 to 0,3000 on M2 Board Dimensions
0,0 to 3500,0 on M2 Board Dimensions
0,-400 to 1000,-400 on M2 Board Dimensions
